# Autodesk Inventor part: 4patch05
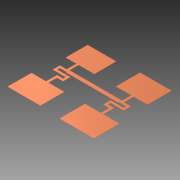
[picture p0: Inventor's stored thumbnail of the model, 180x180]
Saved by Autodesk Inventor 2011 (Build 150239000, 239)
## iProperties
Created: 2014-03
Part Number: 4patch05
Document SubType Name: Modeling
Designer: Evgeny
Density: 1 g/cm^3
Author: Evgeny
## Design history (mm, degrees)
sketch "Эскиз1"
  geometry: L1 (-65, 4.5)-(64.5, 4.5); L2 (64.5, -3)-(64.5, -4.5); L3 (64.5, -4.5)-(-64.5, -4.5); L4 (-64.5, -4.5)-(-64.5, -3); L5 (-71, 3)-(-81.5, 3); L6 (-81.5, -3)-(-64.5, -3); L7 (-71, 3)-(-71, 27); L8 (-71, 27)-(-65, 27); L9 (-65, 27)-(-65, 4.5); L10 (-81.5, 3)-(-87.5, 3); L11 (-87.5, 3)-(-87.5, -14); L12 (-81.5, -9)-(-81.5, -3); L13 (-81.5, -9)-(-49.5, -9); L14 (-49.5, -9)-(-49.5, -25); L15 (-55.5, -15)-(-87.5, -15); L16 (-87.5, -15)-(-87.5, -14); L17 (-55.5, -15)-(-55.5, -21); L18 (-56.5, -27)-(-49.5, -27); L19 (-49.5, -27)-(-49.5, -25); L20 (-56.5, -27)-(-64.5, -27); L21 (-70.5, -37)-(-70.5, -21); L22 (-70.5, -21)-(-55.5, -21); L23 (-70.5, -21)-(-66, -21); L24 (-64.5, -27)-(-64.5, -48); L25 (-64.5, -48)-(-70.5, -48); L26 (-70.5, -48)-(-70.5, -21); L27 (70.5, 3)-(87.5, 3); L28 (87.5, 3)-(87.5, -3); L29 (81.5, -3)-(64.5, -3); L30 (70.5, 3)-(70.5, 27); L31 (70.5, 27)-(64.5, 27); L32 (64.5, 27)-(64.5, 4.5); L33 (81.5, -3)-(81.5, -9); L34 (85.5, -15)-(87.5, -15); L35 (87.5, -15)-(87.5, -3); L36 (85.5, -15)-(55.5, -15); L37 (49.5, -15)-(49.5, -9); L38 (49.5, -9)-(81.5, -9); L39 (49.5, -9)-(55.5, -9); L40 (55.5, -15)-(55.5, -21); L41 (55.5, -27)-(49.5, -27); L42 (49.5, -27)-(49.5, -9); L43 (55.5, -27)-(64.5, -27); L44 (70.5, -27)-(70.5, -21); L45 (70.5, -21)-(55.5, -21); L46 (70.5, -21)-(65, -21); L47 (64.5, -27)-(64.5, -48); L48 (64.5, -48)-(70.5, -48); L49 (70.5, -48)-(70.5, -21); L50 (-97.1, 81)-(-26.5, 81); L51 (-26.5, 81)-(-26.5, 27); L52 (-26.5, 27)-(-97.1, 27); L53 (-97.1, 27)-(-97.1, 81); L54 (26.5, 86.5)-(104.5, 86.5); L55 (104.5, 86.5)-(104.5, 27); L56 (104.5, 27)-(26.5, 27); L57 (26.5, 27)-(26.5, 86.5); L58 (-106.5, -107)-(-25.5, -107); L59 (-25.5, -107)-(-25.5, -48); L60 (-25.5, -48)-(-106.5, -48); L61 (-106.5, -48)-(-106.5, -107); L62 (25.5, -111)-(110.5, -111); L63 (110.5, -111)-(110.5, -48); L64 (110.5, -48)-(25.5, -48)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; 1 further point
  constraints: 130 end point, 28 parallel, 15 horizontal, 14 perpendicular
  dimensions: "d0" = 129 distance between parallel lines of L2 L4; "d1" = 64.5 distance from line of point (0, 0) L4; "d2" = 9 distance between parallel lines of L3 L1; "d3" = 4.5 distance from line of point (0, 0) L3; "d5" = 6 distance between parallel lines of L5 L6; "d6" = 22.5 distance between parallel lines of L8 L1; "d7" = 6 distance between parallel lines of L7 L9; "d8" = 17 distance from line of L4.end L12; "d9" = 6 distance between parallel lines of L11 L12; "d10" = 6 distance between parallel lines of L13 L6; "d11" = 6 distance between parallel lines of L15 L13; "d12" = 15 distance between parallel lines of L19 L24; "d13" = 6 distance between parallel lines of L19 L17; "d14" = 6 distance between parallel lines of L20 L22; "d15" = 6 distance between parallel lines of L26 L24; "d16" = 27 distance between parallel lines of L25 L22; "d17" = 33 distance between parallel lines of L15 L25; "d18" = 64.5 distance from line of L24 point (0, 0); "d19" = 6 distance between parallel lines of L30 L32; "d20" = 17 distance between parallel lines of L33 L2; "d21" = 6 distance between parallel lines of L27 L29; "d22" = 6 distance between parallel lines of L35 L33; "d23" = 6 distance between parallel lines of L36 L38; "d24" = 6 distance between parallel lines of L49 L47; "d25" = 6 distance between parallel lines of L43 L45; "d26" = 6 distance between parallel lines of L42 L40; "d27" = 129 distance between parallel lines of L47 L24; "d28" = 15 distance between parallel lines of L42 L47; "d29" = 33 distance between parallel lines of L36 L48; "d30" = 27 distance between parallel lines of L45 L48; "d31" = 70.6 distance between parallel lines of L53 L51; "d32" = 54 distance between parallel lines of L52 L50; "d33" = 78 distance between parallel lines of L55 L57; "d34" = 59.5 distance between parallel lines of L56 L54; "d35" = 53 distance between parallel lines of L57 L51; "d36" = 26.5 distance from line of L57 point (0, 0); "d37" = 59 distance between parallel lines of L58 L60; "d38" = 81 distance between parallel lines of L59 L61; "d39" = 63 distance between parallel lines of L62 L64; "d40" = 85 distance between parallel lines of L63 L65; "d41" = 51 distance between parallel lines of L65 L59; "d42" = 25.5 distance from line of L59 point (0, 0)
extrude "Выдавливание1" new body sketch "Эскиз1" distance "d43" = 0.5; taper "d44" = 0 deg
node "Твердое тело1"
